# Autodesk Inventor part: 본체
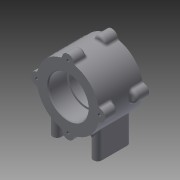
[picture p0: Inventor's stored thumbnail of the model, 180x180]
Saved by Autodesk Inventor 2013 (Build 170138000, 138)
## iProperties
Created: 2015-03
Part Number: 본체
Material: Generic
Document SubType Name: Modeling
Designer: Administrator
Density: 1 g/cm^3
Author: Administrator
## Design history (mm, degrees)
sketch "스케치1"
  geometry: C1 r 37 at (0, 0); 1 further point
  constraints: 1 centre point, 1 coincident
  dimensions: "d0" = 74 diameter of C1
extrude "돌출1" new body sketch "스케치1" stored distance "d1" = 52; taper "d2" = 0 deg
node "작업 평면1"
sketch "스케치2"
  geometry: L1 (-29, 15)-(-29, -15); L2 (-19, 15)-(-19, -15); L3 (19, 15)-(19, -15); L4 (29, 15)-(29, -15); A1 r 5 centre (-24, 15) between (-19, 15) and (-29, 15); A2 r 5 centre (24, 15) between (29, 15) and (19, 15); A3 r 5 centre (24, -15) between (19, -15) and (29, -15); A4 r 5 centre (-24, -15) between (-29, -15) and (-19, -15); 1 further point
  constraints: 8 end point, 8 point on circle, 7 tangent, 4 centre point, 1 parallel
  dimensions: "d7" = 10 diameter of A1; "d8" = 10 diameter of A2; "d9" = 10 diameter of A3; "d10" = 10 diameter of A4; "d11" = 48 distance of A3.centre A4.centre; "d12" = 15 vertical distance of A2.centre point (0, 0); "d13" = 24 horizontal distance of A2.centre point (0, 0); "d14" = 24 horizontal distance of A1.centre point (0, 0); "d15" = 15 vertical distance of A1.centre point (0, 0); "d16" = 15 vertical distance of A4.centre point (0, 0); "d17" = 24 horizontal distance of point (0, 0) A4.centre; "d18" = 24 horizontal distance of A3.centre point (0, 0)
extrude "돌출2" join sketch "스케치2" stored distance "d19" = 52; taper "d20" = 0 deg
sketch "스케치3"
  geometry: C1 r 7 at (0, 37); C2 r 7 at (37, 0); C3 r 7 at (0, -37); C4 r 7 at (-37, 0)
  constraints: 4 centre point
  dimensions: "d21" = 7 radius of C1; "d22" = 7 radius of C2; "d23" = 7 radius of C3; "d24" = 7 radius of C4
extrude "돌출3" join sketch "스케치3" distance "d25" = 15; taper "d26" = 0 deg
sketch "스케치4"
  geometry: A1 r 37 centre (0, 0) between (6.969, 36.338) and (-6.969, 36.338) reference; A2 r 7 centre (0, 37) between (6.969, 36.338) and (-6.969, 36.338) reference; A3 r 37 centre (0, 0) between (36.338, -6.969) and (36.338, 6.969) reference; A4 r 7 centre (37, 0) between (36.338, -6.969) and (36.338, 6.969) reference; A5 r 37 centre (0, 0) between (-36.338, 6.969) and (-36.338, -6.969) reference; A6 r 7 centre (-37, 0) between (-36.338, 6.969) and (-36.338, -6.969) reference; A7 r 37 centre (0, 0) between (-6.969, -36.338) and (6.969, -36.338) reference; A8 r 7 centre (0, -37) between (-6.969, -36.338) and (6.969, -36.338) reference
extrude "돌출4" join sketch "스케치4" distance "d27" = 15; taper "d28" = 0 deg
sketch "스케치5"
  geometry: C1 r 23.5 at (0, 0)
  constraints: 1 centre point
  dimensions: "d30" = 47 diameter of C1
extrude "돌출5" cut sketch "스케치5" distance "d31" = 22; taper "d32" = 0 deg
sketch "스케치6"
  geometry: C1 r 21 at (0, 0); 1 further point
  constraints: 1 centre point, 1 coincident
  dimensions: "d33" = 42 diameter of C1
extrude "돌출6" cut sketch "스케치6" distance "d35" = 8; taper "d36" = 0 deg
sketch "스케치7"
  geometry: C1 r 23.5 at (0, 0) reference
extrude "돌출7" cut sketch "스케치7" distance "d37" = 22; taper "d38" = 0 deg
sketch "스케치8"
  geometry: L1 (-29, 15)-(-29, -15) reference; L2 (-19, -15)-(-19, 15) reference; A1 r 5 centre (24, 15) between (29, 15) and (19, 15) reference; A2 r 5 centre (24, -15) between (19, -15) and (29, -15) reference; A3 r 5 centre (-24, 15) between (-19, 15) and (-29, 15) reference; A4 r 5 centre (-24, -15) between (-29, -15) and (-19, -15) reference; 5 further points
  constraints: 4 coincident
hole "구멍1" sketch "스케치8" at (-24, 15), (24, 15), (24, -15), (-24, -15) diameter "d39" = 4.134; stored, may be unused: countersink angle "d43" = 90 deg, drill point angle "d45" = 118 deg; dims "d40" = 6, "d41" = 4, "d42" = 2, "d44" = 8
sketch "스케치9"
  geometry: A1 r 7 centre (37, 0) between (36.338, -6.969) and (36.338, 6.969) reference; A2 r 7 centre (0, 37) between (6.969, 36.338) and (-6.969, 36.338) reference; A3 r 7 centre (-37, 0) between (-36.338, 6.969) and (-36.338, -6.969) reference; A4 r 7 centre (0, -37) between (-6.969, -36.338) and (6.969, -36.338) reference; 4 further points
  constraints: 4 coincident
hole "구멍2" sketch "스케치9" at (0, 37), (37, 0), (0, -37), (-37, 0) diameter "d46" = 3.242; stored, may be unused: countersink angle "d50" = 90 deg, drill point angle "d52" = 118 deg; dims "d47" = 8, "d48" = 4, "d49" = 2, "d51" = 11
sketch "스케치10"
  geometry: A1 r 7 centre (0, -37) between (-6.969, -36.338) and (6.969, -36.338) reference; A2 r 7 centre (37, 0) between (36.338, -6.969) and (36.338, 6.969) reference; A3 r 7 centre (0, 37) between (6.969, 36.338) and (-6.969, 36.338) reference; A4 r 7 centre (-37, 0) between (-36.338, 6.969) and (-36.338, -6.969) reference; 4 further points
  constraints: 4 coincident
hole "구멍3" sketch "스케치10" at (0, 37), (-37, 0), (0, -37), (37, 0) diameter "d53" = 3.242; stored, may be unused: countersink angle "d57" = 90 deg, drill point angle "d59" = 118 deg; dims "d54" = 8, "d55" = 4, "d56" = 2, "d58" = 11
node "작업 평면3"
  node "작업 평면2"
sketch "스케치11"
  geometry: 2 further points
  constraints: 1 coincident, 1 other
feature "엠보싱1" sketch "스케치11" dims "d22" = 7, "d62" = 0.5, "d63" = 0
chamfer "모따기1" distance "d64" = 1; stored, may be unused: second distance "d65" = 2, angle "d66" = 45 deg
chamfer "모따기2" distance "d67" = 1; stored, may be unused: second distance "d68" = 2, angle "d69" = 45 deg
fillet "모깎기1" dims "d70" = 0.3
fillet "모깎기2" dims "d71" = 3
node "솔리드1"
node "투영된 루프1"
node "투영된 루프2"
node "투영된 루프3"
node "투영된 루프4"
node "투영된 루프5"
other parameters: "d3" = -56, "d60" = 45 deg, "d61" = 37
